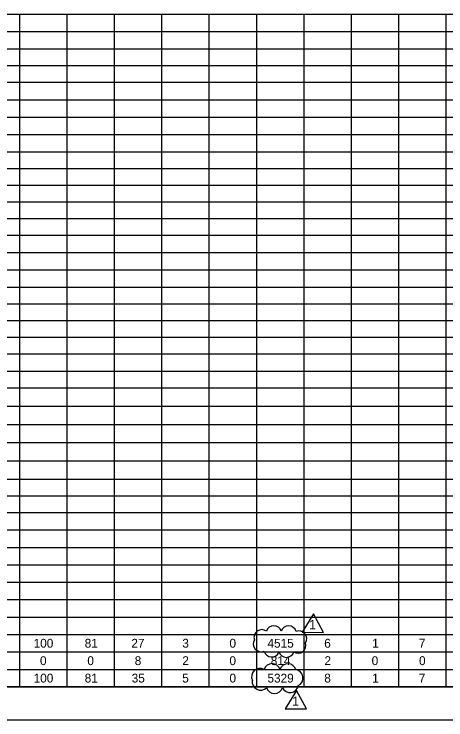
# Model space of a CAD drawing. Extents: x 0 to 34, y 0 to 22.
# Drawn here: x 19.73 to 26.26, y 0 to 10.69 of the extents above; entities that cross this region are included whole.
import ezdxf

# ---------------------------------------------------------------- set-up
doc = ezdxf.new("R2010")
doc.units = 0
for name, color, linetype in [('Default', 7, 'Continuous'), ('SH_Border', 7, 'Continuous'), ('SH_Cut_Line', 7, 'Continuous'), ('SH_Text', 7, 'Continuous')]:
    doc.layers.add(name, color=color, linetype=linetype)

msp = doc.modelspace()

# ---------------------------------------------------------------- linework, layer by layer
at = {"layer": 'Default'}
for points in [[(24.259, 1.606), (24.088, 1.327), (24.408, 1.326)], [(24.001, 0.445), (23.831, 0.167), (24.151, 0.165)]]:
    msp.add_lwpolyline(points, close=True, dxfattribs=at)
for centre, radius, start, end in [((23.657, 1.309), 0.118, 17.5, 162.5), ((23.881, 1.306), 0.118, 16.3904, 161.3904), ((23.475, 1.249), 0.118, 53.5593, 198.5593), ((24.038, 1.231), 0.118, 327.0016, 112.0016), ((23.464, 1.151), 0.118, 148.5071, 293.5071), ((24.026, 1.126), 0.117, 235.3112, 20.3112), ((23.625, 1.071), 0.118, 194.0382, 339.0382), ((23.847, 1.065), 0.118, 197.5, 342.5), ((23.447, 0.653), 0.127, 60.6066, 205.6066), ((23.63, 0.726), 0.127, 17.5, 162.5), ((23.87, 0.723), 0.127, 16.1831, 161.1831), ((23.972, 0.633), 0.127, 296.0565, 81.0565), ((23.457, 0.577), 0.127, 170.0233, 315.0233), ((23.668, 0.525), 0.127, 197.5, 342.5), ((23.903, 0.541), 0.127, 205.1758, 350.1758)]:
    msp.add_arc(centre, radius, start, end, dxfattribs=at)
at = {"layer": 'SH_Border'}
msp.add_lwpolyline([(1.5, 21.5), (33.5, 21.5), (33.5, 0.5), (1.5, 0.5)], close=True, dxfattribs=at)
at = {"layer": 'SH_Cut_Line'}
msp.add_lwpolyline([(0, 0), (34, 0), (34, 22), (0, 22)], close=True, dxfattribs=at)
at = {"layer": 'SH_Text'}
for p, q in [((15.504, 10.692), (21.958, 10.692)), ((19.807, 10.692), (19.807, 10.428)), ((20.524, 10.692), (20.524, 10.428)), ((21.241, 10.692), (21.241, 10.428)), ((21.958, 10.692), (22.676, 10.692)), ((21.958, 10.692), (21.958, 10.428)), ((22.676, 10.692), (24.827, 10.692)), ((22.676, 10.692), (22.676, 10.428)), ((23.393, 10.692), (23.393, 10.428)), ((24.11, 10.692), (24.11, 10.428)), ((24.827, 10.692), (25.544, 10.692)), ((24.827, 10.692), (24.827, 10.428)), ((25.544, 10.692), (26.261, 10.692)), ((25.544, 10.692), (25.544, 10.428)), ((26.261, 10.692), (28.413, 10.692)), ((26.261, 10.692), (26.261, 10.428)), ((15.504, 10.428), (21.958, 10.428)), ((19.807, 10.428), (19.807, 10.164)), ((20.524, 10.428), (20.524, 10.164)), ((21.241, 10.428), (21.241, 10.164)), ((21.958, 10.428), (22.676, 10.428)), ((21.958, 10.428), (21.958, 10.164)), ((22.676, 10.428), (24.827, 10.428)), ((22.676, 10.428), (22.676, 10.164)), ((23.393, 10.428), (23.393, 10.164)), ((24.11, 10.428), (24.11, 10.164)), ((24.827, 10.428), (25.544, 10.428)), ((24.827, 10.428), (24.827, 10.164)), ((25.544, 10.428), (26.261, 10.428)), ((25.544, 10.428), (25.544, 10.164)), ((26.261, 10.428), (28.413, 10.428)), ((26.261, 10.428), (26.261, 10.164)), ((15.504, 10.164), (21.958, 10.164)), ((19.807, 10.164), (19.807, 9.396)), ((20.524, 10.164), (20.524, 9.396)), ((21.241, 10.164), (21.241, 9.396)), ((21.958, 10.164), (22.676, 10.164)), ((21.958, 10.164), (21.958, 9.396)), ((22.676, 10.164), (24.827, 10.164)), ((22.676, 10.164), (22.676, 9.396)), ((23.393, 10.164), (23.393, 9.396)), ((24.11, 10.164), (24.11, 9.396)), ((24.827, 10.164), (25.544, 10.164)), ((24.827, 10.164), (24.827, 9.396)), ((25.544, 10.164), (26.261, 10.164)), ((25.544, 10.164), (25.544, 9.396)), ((26.261, 10.164), (28.413, 10.164)), ((26.261, 10.164), (26.261, 9.396)), ((15.504, 9.912), (21.958, 9.912)), ((21.958, 9.912), (22.676, 9.912)), ((22.676, 9.912), (24.827, 9.912)), ((24.827, 9.912), (25.544, 9.912)), ((25.544, 9.912), (26.261, 9.912)), ((26.261, 9.912), (28.413, 9.912)), ((15.504, 9.66), (21.958, 9.66)), ((21.958, 9.66), (22.676, 9.66)), ((22.676, 9.66), (24.827, 9.66)), ((24.827, 9.66), (25.544, 9.66)), ((25.544, 9.66), (26.261, 9.66)), ((26.261, 9.66), (28.413, 9.66)), ((15.504, 9.396), (21.958, 9.396)), ((19.807, 9.396), (19.807, 9.132)), ((20.524, 9.396), (20.524, 9.132)), ((21.241, 9.396), (21.241, 9.132)), ((21.958, 9.396), (22.676, 9.396)), ((21.958, 9.396), (21.958, 9.132)), ((22.676, 9.396), (24.827, 9.396)), ((22.676, 9.396), (22.676, 9.132)), ((23.393, 9.396), (23.393, 9.132)), ((24.11, 9.396), (24.11, 9.132)), ((24.827, 9.396), (25.544, 9.396)), ((24.827, 9.396), (24.827, 9.132)), ((25.544, 9.396), (26.261, 9.396)), ((25.544, 9.396), (25.544, 9.132)), ((26.261, 9.396), (28.413, 9.396)), ((26.261, 9.396), (26.261, 9.132)), ((15.504, 9.132), (21.958, 9.132)), ((19.807, 9.132), (19.807, 8.868)), ((20.524, 9.132), (20.524, 8.868)), ((21.241, 9.132), (21.241, 8.868)), ((21.958, 9.132), (22.676, 9.132)), ((21.958, 9.132), (21.958, 8.868)), ((22.676, 9.132), (24.827, 9.132)), ((22.676, 9.132), (22.676, 8.868)), ((23.393, 9.132), (23.393, 8.868)), ((24.11, 9.132), (24.11, 8.868)), ((24.827, 9.132), (25.544, 9.132)), ((24.827, 9.132), (24.827, 8.868)), ((25.544, 9.132), (26.261, 9.132)), ((25.544, 9.132), (25.544, 8.868)), ((26.261, 9.132), (28.413, 9.132)), ((26.261, 9.132), (26.261, 8.868)), ((15.504, 8.868), (21.958, 8.868)), ((19.807, 8.868), (19.807, 8.604)), ((20.524, 8.868), (20.524, 8.604)), ((21.241, 8.868), (21.241, 8.604)), ((21.958, 8.868), (22.676, 8.868)), ((21.958, 8.868), (21.958, 8.604)), ((22.676, 8.868), (24.827, 8.868)), ((22.676, 8.868), (22.676, 8.604)), ((23.393, 8.868), (23.393, 8.604)), ((24.11, 8.868), (24.11, 8.604)), ((24.827, 8.868), (25.544, 8.868)), ((24.827, 8.868), (24.827, 8.604)), ((25.544, 8.868), (26.261, 8.868)), ((25.544, 8.868), (25.544, 8.604)), ((26.261, 8.868), (28.413, 8.868)), ((26.261, 8.868), (26.261, 8.604)), ((15.504, 8.604), (21.958, 8.604)), ((19.807, 8.604), (19.807, 7.081)), ((20.524, 8.604), (20.524, 7.081)), ((21.241, 8.604), (21.241, 7.081)), ((21.958, 8.604), (22.676, 8.604)), ((21.958, 8.604), (21.958, 7.081)), ((22.676, 8.604), (24.827, 8.604)), ((22.676, 8.604), (22.676, 7.081)), ((23.393, 8.604), (23.393, 7.081)), ((24.11, 8.604), (24.11, 7.081)), ((24.827, 8.604), (25.544, 8.604)), ((24.827, 8.604), (24.827, 7.081)), ((25.544, 8.604), (26.261, 8.604)), ((25.544, 8.604), (25.544, 7.081)), ((26.261, 8.604), (28.413, 8.604)), ((26.261, 8.604), (26.261, 7.081)), ((15.504, 8.352), (21.958, 8.352)), ((21.958, 8.352), (22.676, 8.352)), ((22.676, 8.352), (24.827, 8.352)), ((24.827, 8.352), (25.544, 8.352)), ((25.544, 8.352), (26.261, 8.352)), ((26.261, 8.352), (28.413, 8.352)), ((15.504, 8.1), (21.958, 8.1)), ((21.958, 8.1), (22.676, 8.1)), ((22.676, 8.1), (24.827, 8.1)), ((24.827, 8.1), (25.544, 8.1)), ((25.544, 8.1), (26.261, 8.1)), ((26.261, 8.1), (28.413, 8.1)), ((15.504, 7.849), (21.958, 7.849)), ((21.958, 7.849), (22.676, 7.849)), ((22.676, 7.849), (24.827, 7.849)), ((24.827, 7.849), (25.544, 7.849)), ((25.544, 7.849), (26.261, 7.849)), ((26.261, 7.849), (28.413, 7.849)), ((15.504, 7.597), (21.958, 7.597)), ((21.958, 7.597), (22.676, 7.597)), ((22.676, 7.597), (24.827, 7.597)), ((24.827, 7.597), (25.544, 7.597)), ((25.544, 7.597), (26.261, 7.597)), ((26.261, 7.597), (28.413, 7.597)), ((15.504, 7.345), (21.958, 7.345)), ((21.958, 7.345), (22.676, 7.345)), ((22.676, 7.345), (24.827, 7.345)), ((24.827, 7.345), (25.544, 7.345)), ((25.544, 7.345), (26.261, 7.345)), ((26.261, 7.345), (28.413, 7.345)), ((15.504, 7.081), (21.958, 7.081)), ((19.807, 7.081), (19.807, 6.817)), ((20.524, 7.081), (20.524, 6.817)), ((21.241, 7.081), (21.241, 6.817)), ((21.958, 7.081), (22.676, 7.081)), ((21.958, 7.081), (21.958, 6.817)), ((22.676, 7.081), (24.827, 7.081)), ((22.676, 7.081), (22.676, 6.817)), ((23.393, 7.081), (23.393, 6.817)), ((24.11, 7.081), (24.11, 6.817)), ((24.827, 7.081), (25.544, 7.081)), ((24.827, 7.081), (24.827, 6.817)), ((25.544, 7.081), (26.261, 7.081)), ((25.544, 7.081), (25.544, 6.817)), ((26.261, 7.081), (28.413, 7.081)), ((26.261, 7.081), (26.261, 6.817)), ((15.504, 6.817), (21.958, 6.817)), ((19.807, 6.817), (19.807, 5.282)), ((20.524, 6.817), (20.524, 5.282)), ((21.241, 6.817), (21.241, 5.282)), ((21.958, 6.817), (22.676, 6.817)), ((21.958, 6.817), (21.958, 5.282)), ((22.676, 6.817), (24.827, 6.817)), ((22.676, 6.817), (22.676, 5.282)), ((23.393, 6.817), (23.393, 5.282)), ((24.11, 6.817), (24.11, 5.282)), ((24.827, 6.817), (25.544, 6.817)), ((24.827, 6.817), (24.827, 5.282)), ((25.544, 6.817), (26.261, 6.817)), ((25.544, 6.817), (25.544, 5.282)), ((26.261, 6.817), (28.413, 6.817)), ((26.261, 6.817), (26.261, 5.282)), ((15.504, 6.553), (21.958, 6.553)), ((21.958, 6.553), (22.676, 6.553)), ((22.676, 6.553), (24.827, 6.553)), ((24.827, 6.553), (25.544, 6.553)), ((25.544, 6.553), (26.261, 6.553)), ((26.261, 6.553), (28.413, 6.553)), ((15.504, 6.301), (21.958, 6.301)), ((21.958, 6.301), (22.676, 6.301)), ((22.676, 6.301), (24.827, 6.301)), ((24.827, 6.301), (25.544, 6.301)), ((25.544, 6.301), (26.261, 6.301)), ((26.261, 6.301), (28.413, 6.301)), ((15.504, 6.049), (21.958, 6.049)), ((21.958, 6.049), (22.676, 6.049)), ((22.676, 6.049), (24.827, 6.049)), ((24.827, 6.049), (25.544, 6.049)), ((25.544, 6.049), (26.261, 6.049)), ((26.261, 6.049), (28.413, 6.049)), ((15.504, 5.798), (21.958, 5.798)), ((21.958, 5.798), (22.676, 5.798)), ((22.676, 5.798), (24.827, 5.798)), ((24.827, 5.798), (25.544, 5.798)), ((25.544, 5.798), (26.261, 5.798)), ((26.261, 5.798), (28.413, 5.798)), ((15.504, 5.546), (21.958, 5.546)), ((21.958, 5.546), (22.676, 5.546)), ((22.676, 5.546), (24.827, 5.546)), ((24.827, 5.546), (25.544, 5.546)), ((25.544, 5.546), (26.261, 5.546)), ((26.261, 5.546), (28.413, 5.546)), ((15.504, 5.282), (21.958, 5.282)), ((19.807, 5.282), (19.807, 4.477)), ((20.524, 5.282), (20.524, 4.477)), ((21.241, 5.282), (21.241, 4.477)), ((21.958, 5.282), (22.676, 5.282)), ((21.958, 5.282), (21.958, 4.477)), ((22.676, 5.282), (24.827, 5.282)), ((22.676, 5.282), (22.676, 4.477)), ((23.393, 5.282), (23.393, 4.477)), ((24.11, 5.282), (24.11, 4.477)), ((24.827, 5.282), (25.544, 5.282)), ((24.827, 5.282), (24.827, 4.477)), ((25.544, 5.282), (26.261, 5.282)), ((25.544, 5.282), (25.544, 4.477)), ((26.261, 5.282), (28.413, 5.282)), ((26.261, 5.282), (26.261, 4.477)), ((15.504, 5.03), (21.958, 5.03)), ((21.958, 5.03), (22.676, 5.03)), ((22.676, 5.03), (24.827, 5.03)), ((24.827, 5.03), (25.544, 5.03)), ((25.544, 5.03), (26.261, 5.03)), ((26.261, 5.03), (28.413, 5.03)), ((15.504, 4.753), (21.958, 4.753)), ((21.958, 4.753), (22.676, 4.753)), ((22.676, 4.753), (24.827, 4.753)), ((24.827, 4.753), (25.544, 4.753)), ((25.544, 4.753), (26.261, 4.753)), ((26.261, 4.753), (28.413, 4.753)), ((15.504, 4.477), (21.958, 4.477)), ((19.807, 4.477), (19.807, 3.646)), ((20.524, 4.477), (20.524, 3.646)), ((21.241, 4.477), (21.241, 3.646)), ((21.958, 4.477), (22.676, 4.477)), ((21.958, 4.477), (21.958, 3.646)), ((22.676, 4.477), (24.827, 4.477)), ((22.676, 4.477), (22.676, 3.646)), ((23.393, 4.477), (23.393, 3.646)), ((24.11, 4.477), (24.11, 3.646)), ((24.827, 4.477), (25.544, 4.477)), ((24.827, 4.477), (24.827, 3.646)), ((25.544, 4.477), (26.261, 4.477)), ((25.544, 4.477), (25.544, 3.646)), ((26.261, 4.477), (28.413, 4.477)), ((26.261, 4.477), (26.261, 3.646)), ((15.504, 4.2), (21.958, 4.2)), ((21.958, 4.2), (22.676, 4.2)), ((22.676, 4.2), (24.827, 4.2)), ((24.827, 4.2), (25.544, 4.2)), ((25.544, 4.2), (26.261, 4.2)), ((26.261, 4.2), (28.413, 4.2)), ((15.504, 3.923), (21.958, 3.923)), ((21.958, 3.923), (22.676, 3.923)), ((22.676, 3.923), (24.827, 3.923)), ((24.827, 3.923), (25.544, 3.923)), ((25.544, 3.923), (26.261, 3.923)), ((26.261, 3.923), (28.413, 3.923)), ((15.504, 3.646), (21.958, 3.646)), ((19.807, 3.646), (19.807, 2.35)), ((20.524, 3.646), (20.524, 2.35)), ((21.241, 3.646), (21.241, 2.35)), ((21.958, 3.646), (22.676, 3.646)), ((21.958, 3.646), (21.958, 2.35)), ((22.676, 3.646), (24.827, 3.646)), ((22.676, 3.646), (22.676, 2.35)), ((23.393, 3.646), (23.393, 2.35)), ((24.11, 3.646), (24.11, 2.35)), ((24.827, 3.646), (25.544, 3.646)), ((24.827, 3.646), (24.827, 2.35)), ((25.544, 3.646), (26.261, 3.646)), ((25.544, 3.646), (25.544, 2.35)), ((26.261, 3.646), (28.413, 3.646)), ((26.261, 3.646), (26.261, 2.35)), ((15.504, 3.395), (21.958, 3.395)), ((21.958, 3.395), (22.676, 3.395)), ((22.676, 3.395), (24.827, 3.395)), ((24.827, 3.395), (25.544, 3.395)), ((25.544, 3.395), (26.261, 3.395)), ((26.261, 3.395), (28.413, 3.395)), ((15.504, 3.143), (21.958, 3.143)), ((21.958, 3.143), (22.676, 3.143)), ((22.676, 3.143), (24.827, 3.143)), ((24.827, 3.143), (25.544, 3.143)), ((25.544, 3.143), (26.261, 3.143)), ((26.261, 3.143), (28.413, 3.143)), ((15.504, 2.879), (21.958, 2.879)), ((21.958, 2.879), (22.676, 2.879)), ((22.676, 2.879), (24.827, 2.879)), ((24.827, 2.879), (25.544, 2.879)), ((25.544, 2.879), (26.261, 2.879)), ((26.261, 2.879), (28.413, 2.879)), ((15.504, 2.614), (21.958, 2.614)), ((21.958, 2.614), (22.676, 2.614)), ((22.676, 2.614), (24.827, 2.614)), ((24.827, 2.614), (25.544, 2.614)), ((25.544, 2.614), (26.261, 2.614)), ((26.261, 2.614), (28.413, 2.614)), ((15.504, 2.35), (21.958, 2.35)), ((19.807, 2.35), (19.807, 1.822)), ((20.524, 2.35), (20.524, 1.822)), ((21.241, 2.35), (21.241, 1.822)), ((21.958, 2.35), (22.676, 2.35)), ((21.958, 2.35), (21.958, 1.822)), ((22.676, 2.35), (24.827, 2.35)), ((22.676, 2.35), (22.676, 1.822)), ((23.393, 2.35), (23.393, 1.822)), ((24.11, 2.35), (24.11, 1.822)), ((24.827, 2.35), (25.544, 2.35)), ((24.827, 2.35), (24.827, 1.822)), ((25.544, 2.35), (26.261, 2.35)), ((25.544, 2.35), (25.544, 1.822)), ((26.261, 2.35), (28.413, 2.35)), ((26.261, 2.35), (26.261, 1.822)), ((15.504, 2.086), (21.958, 2.086)), ((21.958, 2.086), (22.676, 2.086)), ((22.676, 2.086), (24.827, 2.086)), ((24.827, 2.086), (25.544, 2.086)), ((25.544, 2.086), (26.261, 2.086)), ((26.261, 2.086), (28.413, 2.086)), ((15.504, 1.822), (21.958, 1.822)), ((19.807, 1.822), (19.807, 1.558)), ((20.524, 1.822), (20.524, 1.558)), ((21.241, 1.822), (21.241, 1.558)), ((21.958, 1.822), (22.676, 1.822)), ((21.958, 1.822), (21.958, 1.558)), ((22.676, 1.822), (24.827, 1.822)), ((22.676, 1.822), (22.676, 1.558)), ((23.393, 1.822), (23.393, 1.558)), ((24.11, 1.822), (24.11, 1.558)), ((24.827, 1.822), (25.544, 1.822)), ((24.827, 1.822), (24.827, 1.558)), ((25.544, 1.822), (26.261, 1.822)), ((25.544, 1.822), (25.544, 1.558)), ((26.261, 1.822), (28.413, 1.822)), ((26.261, 1.822), (26.261, 1.558)), ((15.504, 1.558), (21.958, 1.558)), ((19.807, 1.558), (19.807, 1.029)), ((20.524, 1.558), (20.524, 1.029)), ((21.241, 1.558), (21.241, 1.029)), ((21.958, 1.558), (22.676, 1.558)), ((21.958, 1.558), (21.958, 1.029)), ((22.676, 1.558), (24.827, 1.558)), ((22.676, 1.558), (22.676, 1.029)), ((23.393, 1.558), (23.393, 1.029)), ((24.11, 1.558), (24.11, 1.029)), ((24.827, 1.558), (25.544, 1.558)), ((24.827, 1.558), (24.827, 1.029)), ((25.544, 1.558), (26.261, 1.558)), ((25.544, 1.558), (25.544, 1.029)), ((26.261, 1.558), (28.413, 1.558)), ((26.261, 1.558), (26.261, 1.029)), ((15.504, 1.293), (21.958, 1.293)), ((21.958, 1.293), (22.676, 1.293)), ((22.676, 1.293), (24.827, 1.293)), ((24.827, 1.293), (25.544, 1.293)), ((25.544, 1.293), (26.261, 1.293)), ((26.261, 1.293), (28.413, 1.293)), ((15.504, 1.029), (21.958, 1.029)), ((19.807, 1.029), (19.807, 0.501)), ((20.524, 1.029), (20.524, 0.501)), ((21.241, 1.029), (21.241, 0.501)), ((21.958, 1.029), (22.676, 1.029)), ((21.958, 1.029), (21.958, 0.501)), ((22.676, 1.029), (24.827, 1.029)), ((22.676, 1.029), (22.676, 0.501)), ((23.393, 1.029), (23.393, 0.501)), ((24.11, 1.029), (24.11, 0.501)), ((24.827, 1.029), (25.544, 1.029)), ((24.827, 1.029), (24.827, 0.501)), ((25.544, 1.029), (26.261, 1.029)), ((25.544, 1.029), (25.544, 0.501)), ((26.261, 1.029), (28.413, 1.029)), ((26.261, 1.029), (26.261, 0.501)), ((15.504, 0.765), (21.958, 0.765)), ((21.958, 0.765), (22.676, 0.765)), ((22.676, 0.765), (24.827, 0.765)), ((24.827, 0.765), (25.544, 0.765)), ((25.544, 0.765), (26.261, 0.765)), ((26.261, 0.765), (28.413, 0.765)), ((15.504, 0.501), (21.958, 0.501)), ((21.958, 0.501), (22.676, 0.501)), ((22.676, 0.501), (24.827, 0.501)), ((24.827, 0.501), (25.544, 0.501)), ((25.544, 0.501), (26.261, 0.501)), ((26.261, 0.501), (28.413, 0.501))]:
    msp.add_line(p, q, dxfattribs=at)

# ---------------------------------------------------------------- texts
at = {"layer": 'Default'}
for p in [(24.192, 1.374), (23.934, 0.213)]:
    msp.add_text('1', height=0.14, dxfattribs=at).set_placement(p)
at = {"layer": 'SH_Text'}
for s, height, p in [('100', 0.1337, (20.022, 1.094)), ('81', 0.1337, (20.795, 1.094)), ('27', 0.1337, (21.501, 1.094)), ('3', 0.134, (22.272, 1.094)), ('0', 0.134, (22.986, 1.094)), ('4515', 0.1337, (23.561, 1.094)), ('6', 0.134, (24.42, 1.094)), ('1', 0.134, (25.146, 1.094)), ('7', 0.134, (25.852, 1.094)), ('0', 0.134, (20.118, 0.83)), ('0', 0.134, (20.835, 0.83)), ('8', 0.134, (21.552, 0.83)), ('2', 0.134, (22.272, 0.83)), ('0', 0.134, (22.986, 0.83)), ('814', 0.1337, (23.611, 0.83)), ('2', 0.134, (24.424, 0.83)), ('0', 0.134, (25.138, 0.83)), ('0', 0.134, (25.855, 0.83)), ('100', 0.1337, (20.022, 0.566)), ('81', 0.1337, (20.795, 0.566)), ('35', 0.1337, (21.506, 0.566)), ('5', 0.134, (22.271, 0.566)), ('0', 0.134, (22.986, 0.566)), ('5329', 0.1337, (23.561, 0.566)), ('8', 0.134, (24.421, 0.566)), ('1', 0.134, (25.146, 0.566)), ('7', 0.134, (25.852, 0.566))]:
    msp.add_text(s, height=height, dxfattribs=at).set_placement(p)

doc.saveas('drawing.dxf')
